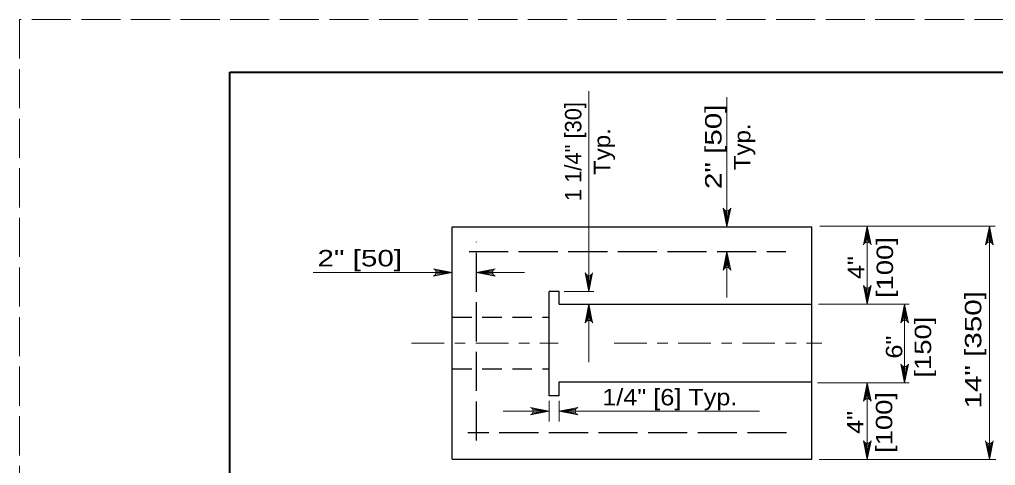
# Model space of a CAD drawing. Extents: x 1083.1 to 1117.1, y 697.4 to 741.4.
# Drawn here: x 1083.13 to 1092.41, y 737.11 to 741.35 of the extents above; entities that cross this region are included whole.
import ezdxf
from ezdxf.enums import TextEntityAlignment as Align

# ---------------------------------------------------------------- set-up
doc = ezdxf.new("R2010")
doc.units = 0
doc.header["$LTSCALE"] = 0.062
for name, pattern in [('DOT_DASHED', [7.7, 5, -1.2, 0.3, -1.2]), ('LONG_DASHED', [7.5, 6, -1.5]), ('MEDIUM_DASHED', [4.5, 3, -1.5])]:
    doc.linetypes.add(name, pattern=pattern)
doc.layers.add('1', color=7, linetype='Continuous', lineweight=13)

msp = doc.modelspace()

# ---------------------------------------------------------------- linework, layer by layer
at = {"layer": '1', "lineweight": 25}
for p, q in [((1085.12642, 740.85408), (1116.62642, 740.85408)), ((1087.24225, 739.381), (1090.66425, 739.381)), ((1087.24225, 737.1685), (1087.24225, 739.381)), ((1090.66425, 737.1685), (1090.66425, 739.381)), ((1087.47325, 739.146), (1087.47325, 739.14825)), ((1088.16508, 737.77392), (1088.16508, 738.76525)), ((1088.2595, 738.6435), (1090.66425, 738.6435)), ((1088.2595, 737.906), (1090.66425, 737.906)), ((1088.2595, 737.77392), (1088.2595, 737.906)), ((1088.2595, 737.77392), (1088.16508, 737.77392)), ((1087.24225, 737.1685), (1090.66425, 737.1685))]:
    msp.add_line(p, q, dxfattribs=at)
at = {"layer": '1'}
for p, q in [((1088.54267, 738.76525), (1088.54267, 740.67058)), ((1089.85542, 739.38092), (1089.85542, 740.61425)), ((1089.833, 739.54117), (1089.85542, 739.38092)), ((1089.84408, 739.53575), (1089.85542, 739.38092)), ((1089.88025, 739.543), (1089.85542, 739.38092)), ((1089.86983, 739.53692), (1089.85542, 739.38092)), ((1089.85542, 739.53408), (1089.85542, 739.38092)), ((1092.40692, 739.3875), (1090.73767, 739.3875)), ((1091.16575, 739.22583), (1091.1905, 739.388)), ((1091.17608, 739.232), (1091.1905, 739.388)), ((1091.1905, 738.65708), (1091.1905, 739.388)), ((1091.1905, 739.23483), (1091.1905, 739.388)), ((1091.20183, 739.23317), (1091.1905, 739.388)), ((1091.21292, 739.22775), (1091.1905, 739.388)), ((1092.3265, 739.22533), (1092.35125, 739.3875)), ((1092.33683, 739.2315), (1092.35125, 739.3875)), ((1092.35125, 737.16583), (1092.35125, 739.3875)), ((1092.35125, 739.23433), (1092.35125, 739.3875)), ((1092.36258, 739.23267), (1092.35125, 739.3875)), ((1092.37367, 739.22725), (1092.35125, 739.3875)), ((1089.83067, 738.98383), (1089.85542, 739.146)), ((1089.841, 738.99), (1089.85542, 739.146)), ((1089.85542, 738.707), (1089.85542, 739.146)), ((1089.85542, 738.99283), (1089.85542, 739.146)), ((1089.86675, 738.99117), (1089.85542, 739.146)), ((1089.87783, 738.98575), (1089.85542, 739.146)), ((1087.24225, 738.94708), (1085.9185, 738.94708)), ((1087.08008, 738.92225), (1087.24225, 738.94708)), ((1087.082, 738.9695), (1087.24225, 738.94708)), ((1087.08625, 738.93267), (1087.24225, 738.94708)), ((1087.08742, 738.95842), (1087.24225, 738.94708)), ((1087.08908, 738.94708), (1087.24225, 738.94708)), ((1087.6335, 738.9695), (1087.47325, 738.94708)), ((1087.62808, 738.95842), (1087.47325, 738.94708)), ((1087.92867, 738.94708), (1087.47325, 738.94708)), ((1087.62642, 738.94708), (1087.47325, 738.94708)), ((1087.62925, 738.93267), (1087.47325, 738.94708)), ((1087.63542, 738.92225), (1087.47325, 738.94708)), ((1088.52025, 738.9255), (1088.54267, 738.76525)), ((1088.53142, 738.92008), (1088.54267, 738.76525)), ((1088.5675, 738.92733), (1088.54267, 738.76525)), ((1088.55708, 738.92125), (1088.54267, 738.76525)), ((1088.54267, 738.91842), (1088.54267, 738.76525)), ((1088.30667, 738.76525), (1088.58992, 738.76525)), ((1091.16808, 738.80467), (1091.1905, 738.64442)), ((1091.17917, 738.79917), (1091.1905, 738.64442)), ((1091.21525, 738.8065), (1091.1905, 738.64442)), ((1091.20492, 738.80042), (1091.1905, 738.64442)), ((1091.1905, 738.79758), (1091.1905, 738.64442)), ((1088.51792, 738.48133), (1088.54267, 738.6435)), ((1088.52833, 738.4875), (1088.54267, 738.6435)), ((1088.54267, 738.6435), (1088.54267, 738.0935)), ((1088.54267, 738.49033), (1088.54267, 738.6435)), ((1088.554, 738.48867), (1088.54267, 738.6435)), ((1088.56517, 738.48325), (1088.54267, 738.6435)), ((1091.58725, 738.6455), (1090.72667, 738.6455)), ((1091.5205, 738.48225), (1091.54533, 738.64442)), ((1091.53092, 738.48842), (1091.54533, 738.64442)), ((1091.54533, 737.89775), (1091.54533, 738.64442)), ((1091.54533, 738.49125), (1091.54533, 738.64442)), ((1091.55667, 738.48958), (1091.54533, 738.64442)), ((1091.56775, 738.48417), (1091.54533, 738.64442)), ((1091.52292, 738.058), (1091.54533, 737.89775)), ((1091.534, 738.05258), (1091.54533, 737.89775)), ((1091.57008, 738.05992), (1091.54533, 737.89775)), ((1091.55975, 738.05375), (1091.54533, 737.89775)), ((1091.54533, 738.05092), (1091.54533, 737.89775)), ((1091.58725, 737.89775), (1090.71567, 737.89775)), ((1091.16575, 737.73558), (1091.1905, 737.89775)), ((1091.17608, 737.74175), (1091.1905, 737.89775)), ((1091.1905, 737.74458), (1091.1905, 737.89775)), ((1091.20183, 737.74292), (1091.1905, 737.89775)), ((1091.21292, 737.7375), (1091.1905, 737.89775)), ((1091.1905, 737.16733), (1091.1905, 737.89775)), ((1088.00483, 737.64883), (1088.16508, 737.62642)), ((1088.16508, 737.72475), (1088.16508, 737.52808)), ((1088.2595, 737.72475), (1088.2595, 737.52808)), ((1088.41975, 737.64883), (1088.2595, 737.62642)), ((1088.16508, 737.62642), (1087.72758, 737.62642)), ((1088.003, 737.60167), (1088.16508, 737.62642)), ((1088.00908, 737.61208), (1088.16508, 737.62642)), ((1088.01025, 737.63775), (1088.16508, 737.62642)), ((1088.01192, 737.62642), (1088.16508, 737.62642)), ((1088.41433, 737.63775), (1088.2595, 737.62642)), ((1088.2595, 737.62642), (1090.16375, 737.62642)), ((1088.41267, 737.62642), (1088.2595, 737.62642)), ((1088.4155, 737.61208), (1088.2595, 737.62642)), ((1088.42167, 737.60167), (1088.2595, 737.62642)), ((1091.16808, 737.32758), (1091.1905, 737.16733)), ((1091.17917, 737.32217), (1091.1905, 737.16733)), ((1091.21525, 737.32942), (1091.1905, 737.16733)), ((1091.20492, 737.32333), (1091.1905, 737.16733)), ((1091.1905, 737.3205), (1091.1905, 737.16733)), ((1092.32883, 737.32608), (1092.35125, 737.16583)), ((1092.33992, 737.32067), (1092.35125, 737.16583)), ((1092.376, 737.328), (1092.35125, 737.16583)), ((1092.36567, 737.32183), (1092.35125, 737.16583)), ((1092.35125, 737.319), (1092.35125, 737.16583)), ((1092.4125, 737.16733), (1090.73225, 737.16733))]:
    msp.add_line(p, q, dxfattribs=at)
at = {"layer": '1', "linetype": 'LONG_DASHED', "lineweight": 25}
for p, q in [((1087.47325, 737.3465), (1087.47325, 739.23783)), ((1087.40192, 739.146), (1090.41658, 739.146)), ((1090.42208, 737.42075), (1087.38992, 737.42075))]:
    msp.add_line(p, q, dxfattribs=at)
at = {"layer": '1', "linetype": 'MEDIUM_DASHED', "lineweight": 25}
for p, q in [((1087.24225, 738.52058), (1088.16508, 738.52058)), ((1087.24225, 738.02892), (1088.16317, 738.02892))]:
    msp.add_line(p, q, dxfattribs=at)
at = {"layer": '1', "linetype": 'DOT_DASHED'}
for p, q in [((1086.85625, 738.27475), (1088.24983, 738.27475)), ((1088.78242, 738.27475), (1090.75775, 738.27475))]:
    msp.add_line(p, q, dxfattribs=at)
at = {"layer": '1', "linetype": 'LONG_DASHED'}
msp.add_lwpolyline([(1083.12642, 719.35408), (1117.12642, 719.35408), (1117.12642, 741.35408), (1083.12642, 741.35408)], close=True, dxfattribs=at)
at = {"layer": '1', "lineweight": 25}
for points in [[(1116.62642, 719.85408), (1085.12642, 719.85408), (1085.12642, 740.85408)], [(1088.2595, 738.6435), (1088.2595, 738.76525), (1088.16508, 738.76525)]]:
    msp.add_lwpolyline(points, dxfattribs=at)
at = {"layer": '1', "lineweight": 40}
msp.add_lwpolyline([(1085.12642, 740.85408), (1116.62642, 740.85408), (1116.62642, 719.85408), (1085.12642, 719.85408)], close=True, dxfattribs=at)
msp.add_lwpolyline([(1085.12642, 740.85408), (1116.62642, 740.85408), (1116.62642, 719.85408), (1085.12642, 719.85408)], close=True, dxfattribs=at)
at = {"layer": '1'}
for points in [[(1089.89083, 739.55792), (1089.85542, 739.38092), (1089.82, 739.55792)], [(1091.15508, 739.211), (1091.1905, 739.388), (1091.22592, 739.211)], [(1092.31583, 739.2105), (1092.35125, 739.3875), (1092.38667, 739.2105)], [(1089.82, 738.969), (1089.85542, 739.146), (1089.89083, 738.969)], [(1087.06525, 738.91167), (1087.24225, 738.94708), (1087.06525, 738.9825)], [(1087.65025, 738.91167), (1087.47325, 738.94708), (1087.65025, 738.9825)], [(1088.57808, 738.94225), (1088.54267, 738.76525), (1088.50733, 738.94225)], [(1091.22592, 738.82142), (1091.1905, 738.64442), (1091.15508, 738.82142)], [(1088.50733, 738.4665), (1088.54267, 738.6435), (1088.57808, 738.4665)], [(1091.50992, 738.46742), (1091.54533, 738.64442), (1091.58075, 738.46742)], [(1091.58075, 738.07475), (1091.54533, 737.89775), (1091.50992, 738.07475)], [(1091.15508, 737.72075), (1091.1905, 737.89775), (1091.22592, 737.72075)], [(1087.98808, 737.59108), (1088.16508, 737.62642), (1087.98808, 737.66183)], [(1088.4365, 737.59108), (1088.2595, 737.62642), (1088.4365, 737.66183)], [(1091.22592, 737.34433), (1091.1905, 737.16733), (1091.15508, 737.34433)], [(1092.38667, 737.34283), (1092.35125, 737.16583), (1092.31583, 737.34283)]]:
    msp.add_lwpolyline(points, dxfattribs=at)
for centre, start, end in [((1089.8554, 739.5722), 202.08782, 337.91395), ((1091.19054, 739.19669), 22.08782, 157.91395), ((1092.35123, 739.1962), 22.08782, 157.91395), ((1087.05096, 738.9471), 292.08605, 67.91218), ((1087.66454, 738.9471), 112.08782, 247.91395), ((1089.85547, 738.95469), 22.08782, 157.91395), ((1088.54267, 738.95654), 202.08782, 337.91395), ((1091.19046, 738.83568), 202.08782, 337.91395), ((1088.54275, 738.45221), 22.08782, 157.91395), ((1091.54536, 738.4531), 22.08782, 157.91395), ((1091.54528, 738.08904), 202.08782, 337.91395), ((1091.19054, 737.70645), 22.08782, 157.91395), ((1087.97381, 737.62648), 292.08605, 67.91218), ((1088.4508, 737.62648), 112.08782, 247.91395), ((1091.19046, 737.35862), 202.08782, 337.91395), ((1092.35115, 737.35714), 202.08782, 337.91395)]:
    msp.add_arc(centre, 0.0382, start, end, dxfattribs=at)

# ---------------------------------------------------------------- texts
msp.add_text('1 1/4" [30]', height=0.156, rotation=90, dxfattribs=at).set_placement((1088.47083, 740.09704), align=Align.CENTER)
for s, width, p in [('2" [50]', 1.35, (1089.80383, 740.14271)), ('Typ.', 1.1, (1090.07783, 740.14262)), ('Typ.', 1.1, (1088.74483, 740.09704)), ('[100]', 1.25, (1091.43517, 738.99317)), ('4"', 1.15, (1091.16117, 738.99317)), ('[150]', 1.25, (1091.79742, 738.23633)), ('6"', 1.15, (1091.52342, 738.23633)), ('[100]', 1.25, (1091.42808, 737.51917)), ('4"', 1.15, (1091.15408, 737.51917))]:
    msp.add_text(s, height=0.156, rotation=90, dxfattribs=dict(at, width=width)).set_placement(p, align=Align.CENTER)
at = {"layer": '1', "width": 1.35}
msp.add_text('2" [50]', height=0.156, dxfattribs=at).set_placement((1085.96083, 739.00467))
msp.add_text('14" [350]', height=0.156, rotation=90, dxfattribs=at).set_placement((1092.275, 737.65183))
at = {"layer": '1', "width": 1.15}
msp.add_text('1/4" [6] Typ.', height=0.156, dxfattribs=at).set_placement((1089.312, 737.68192), align=Align.CENTER)

doc.saveas('drawing.dxf')
